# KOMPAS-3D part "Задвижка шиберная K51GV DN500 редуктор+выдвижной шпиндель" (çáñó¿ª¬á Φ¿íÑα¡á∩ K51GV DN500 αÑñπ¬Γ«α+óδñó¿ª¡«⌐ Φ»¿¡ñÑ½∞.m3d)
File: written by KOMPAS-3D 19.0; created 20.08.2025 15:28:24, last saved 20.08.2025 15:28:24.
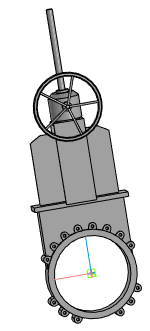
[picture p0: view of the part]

Document properties: Полное имя файла: Задвижка шиберная K51GV DN500 редуктор+выдвижной шпиндель.a3d

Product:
- Part/product: Задвижка шиберная K51GV DN500 редуктор+выдвижной шпиндель
    Масса: 262.237

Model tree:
1. Операция без истории:1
